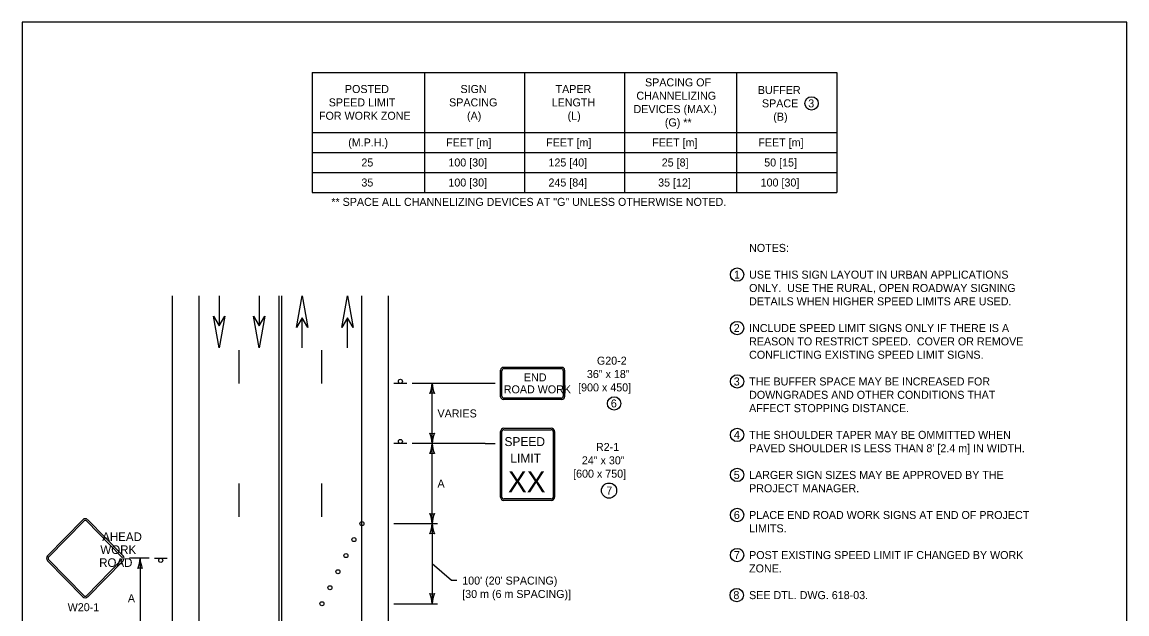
# Model space of a CAD drawing. Extents: x 49991.4 to 50021, y 49987.6 to 50011.4.
# Drawn here: x 50000.34 to 50008.61, y 50006.83 to 50011.26 of the extents above; entities that cross this region are included whole.
import ezdxf

# ---------------------------------------------------------------- set-up
doc = ezdxf.new("R2010")
doc.units = 0
for name, color, linetype in [('Level 1', 7, 'Continuous'), ('Level 2', 7, 'Continuous'), ('Level 3', 7, 'Continuous')]:
    doc.layers.add(name, color=color, linetype=linetype)

msp = doc.modelspace()

# ---------------------------------------------------------------- linework, layer by layer
at = {"layer": 'Level 1'}
for p, q in [((50001.4626, 50001.1514), (50001.4626, 50009.2134)), ((50001.6625, 50001.1514), (50001.6625, 50009.2134)), ((50001.8124, 50009.2134), (50001.8124, 50008.9875)), ((50001.8128, 50009.2134), (50001.8128, 50008.9875)), ((50002.1118, 50009.2134), (50002.1118, 50008.9875)), ((50002.1122, 50009.2134), (50002.1122, 50008.9875)), ((50002.2625, 50001.1514), (50002.2625, 50009.2134)), ((50002.2825, 50001.1514), (50002.2825, 50009.2134)), ((50002.8825, 50006.6477), (50002.8825, 50009.2134)), ((50003.0824, 50001.1514), (50003.0824, 50009.2134)), ((50002.4341, 50008.8233), (50002.4341, 50009.0492)), ((50002.4343, 50008.8233), (50002.4343, 50009.0492)), ((50002.7735, 50008.8232), (50002.7735, 50009.0491)), ((50002.7737, 50008.8232), (50002.7737, 50009.0491)), ((50001.9626, 50008.5574), (50001.9626, 50008.8074)), ((50002.5826, 50008.5574), (50002.5826, 50008.8074)), ((50003.9212, 50008.4574), (50003.9212, 50008.6574)), ((50003.9312, 50008.4624), (50003.9312, 50008.6524)), ((50004.3812, 50008.6774), (50003.9412, 50008.6774)), ((50004.3762, 50008.6674), (50003.9462, 50008.6674)), ((50004.3912, 50008.6524), (50004.3912, 50008.4624)), ((50004.4012, 50008.6574), (50004.4012, 50008.4574)), ((50003.2184, 50008.5574), (50003.1224, 50008.5574)), ((50004.3811, 50008.4374), (50003.9411, 50008.4374)), ((50004.3762, 50008.4474), (50003.9462, 50008.4474)), ((50003.9211, 50007.7066), (50003.9211, 50008.196)), ((50003.9316, 50007.7066), (50003.9316, 50008.196)), ((50003.9464, 50008.2213), (50004.3008, 50008.2213)), ((50003.9464, 50008.2108), (50004.3008, 50008.2108)), ((50004.1236, 50008.2213), (50004.1236, 50008.2213)), ((50004.3156, 50008.196), (50004.3156, 50007.7066)), ((50004.3261, 50008.196), (50004.3261, 50007.7066)), ((50003.2184, 50008.1074), (50003.1224, 50008.1074)), ((50001.9626, 50007.5574), (50001.9626, 50007.8074)), ((50002.5826, 50007.5574), (50002.5826, 50007.8074)), ((50004.3008, 50007.6918), (50003.9464, 50007.6918)), ((50004.3008, 50007.6812), (50003.9464, 50007.6812)), ((50000.5255, 50007.2658), (50000.7907, 50007.5365)), ((50000.5344, 50007.2571), (50000.7996, 50007.5278)), ((50000.8182, 50007.5278), (50001.0834, 50007.2571)), ((50000.827, 50007.5365), (50001.0922, 50007.2658)), ((50000.7996, 50006.9675), (50000.5344, 50007.2382)), ((50001.0834, 50007.2382), (50000.8182, 50006.9675)), ((50001.3266, 50007.2477), (50001.4226, 50007.2477)), ((50000.7907, 50006.9588), (50000.5255, 50007.2295)), ((50001.0922, 50007.2295), (50000.827, 50006.9588))]:
    msp.add_line(p, q, dxfattribs=at)
for points in [[(50008.6146, 50011.2628), (50000.3356, 50011.2628), (50000.3356, 50000.0624), (50008.6146, 50000.0624)], [(50002.3923, 50008.9769), (50002.4341, 50009.2134), (50002.4759, 50008.9769), (50002.4341, 50009.0491)], [(50002.7317, 50008.9768), (50002.7735, 50009.2133), (50002.8153, 50008.9768), (50002.7735, 50009.049)], [(50001.8544, 50009.0598), (50001.8128, 50008.8233), (50001.7708, 50009.0598), (50001.8128, 50008.9876)], [(50002.1538, 50009.0598), (50002.1122, 50008.8233), (50002.0702, 50009.0598), (50002.1122, 50008.9876)]]:
    msp.add_lwpolyline(points, close=True, dxfattribs=at)
for centre, radius in [((50003.1704, 50008.5726), 0.0152), ((50003.1704, 50008.1226), 0.0152), ((50002.8825, 50007.5074), 0.015), ((50002.8225, 50007.3874), 0.015), ((50001.3747, 50007.2325), 0.0152), ((50002.7626, 50007.2674), 0.015), ((50002.7026, 50007.1474), 0.015), ((50002.6426, 50007.0274), 0.015), ((50002.5826, 50006.9074), 0.015)]:
    msp.add_circle(centre, radius, dxfattribs=at)
for centre, radius, start, end in [((50003.9412, 50008.6574), 0.02, 90, 180), ((50003.9462, 50008.6524), 0.015, 90, 180), ((50004.3762, 50008.6524), 0.015, 360, 90), ((50004.3812, 50008.6574), 0.02, 360, 90), ((50003.9411, 50008.4574), 0.02, 180, 270), ((50003.9462, 50008.4624), 0.015, 180, 270), ((50004.3762, 50008.4624), 0.015, 270, 360), ((50004.3811, 50008.4574), 0.02, 270, 360), ((50003.9464, 50008.196), 0.0253, 90, 180), ((50003.9464, 50008.196), 0.0148, 90, 180), ((50004.3008, 50008.196), 0.0253, 0, 90), ((50004.3008, 50008.196), 0.0148, 0, 90), ((50003.9464, 50007.7066), 0.0253, 180, 270), ((50003.9464, 50007.7066), 0.0148, 180, 270), ((50004.3008, 50007.7066), 0.0148, 270, 360), ((50004.3008, 50007.7066), 0.0253, 270, 360)]:
    msp.add_arc(centre, radius, start, end, dxfattribs=at)
for centre, major_axis, ratio, start_param, end_param in [((50000.8089, 50007.5183), (0, 0.0258), 0.98963, 5.497795, 7.068583), ((50000.8089, 50007.5183), (0, 0.0134), 0.98, 5.497795, 7.068583), ((50000.5437, 50007.2477), (0, -0.0258), 0.98963, 3.926991, 5.497787), ((50000.5437, 50007.2477), (0, -0.0134), 0.98, 3.926991, 5.497787), ((50001.0741, 50007.2477), (0, -0.0134), 0.98, 0.785394, 2.356194), ((50001.0741, 50007.2477), (0, -0.0258), 0.98963, 0.785394, 2.356194), ((50000.8089, 50006.9771), (0, -0.0258), 0.98963, 5.497787, 7.068583), ((50000.8089, 50006.9771), (0, -0.0134), 0.98, 5.497787, 7.068583)]:
    msp.add_ellipse(centre, major_axis=major_axis, ratio=ratio, start_param=start_param, end_param=end_param, dxfattribs=at)
at = {"layer": 'Level 2'}
for p, q in [((50002.5101, 50010.8866), (50006.4401, 50010.8866)), ((50002.5101, 50010.8866), (50002.5101, 50009.9866)), ((50003.3501, 50010.8866), (50003.3501, 50009.9866)), ((50004.1001, 50010.8866), (50004.1001, 50009.9866)), ((50004.8501, 50010.8866), (50004.8501, 50009.9866)), ((50005.6901, 50010.8866), (50005.6901, 50009.9866)), ((50006.4401, 50010.8866), (50006.4401, 50009.9866)), ((50002.5101, 50010.4366), (50006.4401, 50010.4366)), ((50002.5101, 50010.2866), (50006.4401, 50010.2866)), ((50002.5101, 50010.1366), (50006.4401, 50010.1366)), ((50002.5101, 50009.9866), (50006.4401, 50009.9866))]:
    msp.add_line(p, q, dxfattribs=at)
for centre, radius in [((50006.2517, 50010.6543), 0.0501), ((50005.6934, 50009.3719), 0.0501), ((50005.6934, 50008.9719), 0.0501), ((50005.6934, 50008.5719), 0.0501), ((50004.7717, 50008.4073), 0.0501), ((50005.6934, 50008.1719), 0.0501), ((50005.6934, 50007.8719), 0.0501), ((50004.7341, 50007.7544), 0.0569), ((50005.6934, 50007.5719), 0.0501), ((50005.6934, 50007.2719), 0.0501), ((50005.6905, 50006.9719), 0.0501)]:
    msp.add_circle(centre, radius, dxfattribs=at)
at = {"layer": 'Level 3'}
for p, q in [((50003.8812, 50008.5574), (50003.2584, 50008.5574)), ((50003.4084, 50008.1074), (50003.4084, 50008.5574)), ((50003.8053, 50008.1074), (50003.2584, 50008.1074)), ((50003.4084, 50007.5074), (50003.4084, 50008.1074)), ((50003.1224, 50007.5074), (50003.4484, 50007.5074)), ((50003.4084, 50007.5074), (50003.4084, 50006.9074)), ((50001.2866, 50007.2477), (50001.1396, 50007.2477)), ((50001.2196, 50007.2477), (50001.2196, 50006.6477)), ((50003.1224, 50006.9074), (50003.4484, 50006.9074))]:
    msp.add_line(p, q, dxfattribs=at)
for points in [[(50003.8053, 50008.1074), (50003.8812, 50008.1074)], [(50003.5937, 50007.0806), (50003.5537, 50007.0806), (50003.4084, 50007.2074)]]:
    msp.add_lwpolyline(points, dxfattribs=at)
for centre, radius, start, end in [((50003.1863, 50008.5666), 0.2223, 337.45601, 357.63952), ((50003.6411, 50008.5689), 0.233, 182.82731, 202.07716), ((50003.4084, 50008.4292), 0.0548, 72.13882, 107.86118), ((50003.4084, 50008.2356), 0.0548, 252.13882, 287.86118), ((50003.1757, 50008.0959), 0.233, 2.82731, 22.07716), ((50003.6305, 50008.0982), 0.2223, 157.45601, 177.63952), ((50003.1863, 50008.1166), 0.2223, 337.45601, 357.63952), ((50003.6411, 50008.1189), 0.233, 182.82731, 202.07716), ((50003.4084, 50007.9792), 0.0548, 72.13882, 107.86118), ((50003.4084, 50007.6356), 0.0548, 252.13882, 287.86118), ((50003.1757, 50007.4959), 0.233, 2.82731, 22.07716), ((50003.6305, 50007.4982), 0.2223, 157.45601, 177.63952), ((50003.1863, 50007.5166), 0.2223, 337.45601, 357.63952), ((50003.1863, 50007.5166), 0.2223, 337.45601, 357.63952), ((50003.6411, 50007.5189), 0.233, 182.82731, 202.07716), ((50003.6411, 50007.5189), 0.233, 182.82731, 202.07716), ((50003.4084, 50007.3792), 0.0548, 72.13882, 107.86118), ((50003.4084, 50007.3792), 0.0548, 72.13882, 107.86118), ((50000.9975, 50007.2569), 0.2223, 337.45601, 357.63952), ((50001.4523, 50007.2592), 0.233, 182.82731, 202.07716), ((50001.2196, 50007.1195), 0.0548, 72.13882, 107.86118), ((50003.4084, 50007.0356), 0.0548, 252.13882, 287.86118), ((50003.1757, 50006.8959), 0.233, 2.82731, 22.07716), ((50003.4084, 50007.0356), 0.0548, 252.13882, 287.86118), ((50003.1757, 50006.8959), 0.233, 2.82731, 22.07716), ((50003.6305, 50006.8982), 0.2223, 157.45601, 177.63952), ((50003.6305, 50006.8982), 0.2223, 157.45601, 177.63952)]:
    msp.add_arc(centre, radius, start, end, dxfattribs=at)

# ---------------------------------------------------------------- texts
at = {"layer": 'Level 1'}
for s, height, p in [('END', 0.06, (50004.096, 50008.5728)), ('ROAD WORK', 0.06, (50003.9453, 50008.4828)), ('AHEAD', 0.06453, (50000.9359, 50007.3767)), ('WORK', 0.06453, (50000.9221, 50007.2799)), ('ROAD', 0.06453, (50000.9131, 50007.1832))]:
    msp.add_text(s, height=height, rotation=360, dxfattribs=at).set_placement(p)
for s, height, p in [('SPEED', 0.06695, (50003.9505, 50008.0881)), ('LIMIT', 0.06695, (50003.9948, 50007.9643)), ('XX', 0.15772, (50003.9765, 50007.7423))]:
    msp.add_text(s, height=height, dxfattribs=at).set_placement(p)
at = {"layer": 'Level 2'}
for s, p in [('POSTED', (50002.7548, 50010.7316)), ('SIGN', (50003.6208, 50010.7316)), ('TAPER', (50004.3334, 50010.7316)), ('SPACING OF', (50005.0036, 50010.7816)), ('CHANNELIZING', (50004.9389, 50010.6816)), ('BUFFER', (50005.849, 50010.7243)), ('SPEED LIMIT', (50002.6335, 50010.6316)), ('SPACING', (50003.5357, 50010.6316)), ('LENGTH', (50004.3042, 50010.6316)), ('DEVICES (MAX.)', (50004.9175, 50010.5816)), ('SPACE', (50005.8798, 50010.6243)), ('3', (50006.2267, 50010.6244)), ('FOR WORK ZONE', (50002.5605, 50010.5316)), ('(A)', (50003.6698, 50010.5316)), ('(L)', (50004.4235, 50010.5316)), ('(G) **', (50005.1522, 50010.4816)), ('(B)', (50005.965, 50010.5243)), ('(M.P.H.)', (50002.7794, 50010.3316)), ('FEET [m]', (50003.5128, 50010.3316)), ('FEET [m]', (50004.2628, 50010.3316)), ('FEET [m]', (50005.0578, 50010.3316)), ('FEET [m]', (50005.8528, 50010.3316)), ('25', (50002.8783, 50010.1816)), ('100 [30]', (50003.53, 50010.1816)), ('125 [40]', (50004.28, 50010.1816)), ('25 [8]', (50005.1288, 50010.1816)), ('50 [15]', (50005.8969, 50010.1816)), ('35', (50002.8783, 50010.0316)), ('100 [30]', (50003.53, 50010.0316)), ('245 [84]', (50004.28, 50010.0316)), ('35 [12]', (50005.1019, 50010.0316)), ('100 [30]', (50005.87, 50010.0316)), ('** SPACE ALL CHANNELIZING DEVICES AT "G" UNLESS OTHERWISE NOTED.', (50002.6529, 50009.8866)), ('NOTES:', (50005.7835, 50009.5419)), ('1', (50005.6707, 50009.3419)), ('USE THIS SIGN LAYOUT IN URBAN APPLICATIONS', (50005.7835, 50009.3419)), ('ONLY.  USE THE RURAL, OPEN ROADWAY SIGNING', (50005.7835, 50009.2419)), ('DETAILS WHEN HIGHER SPEED LIMITS ARE USED.', (50005.7835, 50009.1419)), ('2', (50005.6684, 50008.942)), ('INCLUDE SPEED LIMIT SIGNS ONLY IF THERE IS A', (50005.7835, 50008.9419)), ('REASON TO RESTRICT SPEED.  COVER OR REMOVE', (50005.7835, 50008.8419)), ('CONFLICTING EXISTING SPEED LIMIT SIGNS.', (50005.7835, 50008.7419)), ('G20-2', (50004.6431, 50008.6974)), ('36" x 18"', (50004.5679, 50008.5974)), ('[900 x 450]', (50004.5023, 50008.4974)), ('3', (50005.6684, 50008.542)), ('THE BUFFER SPACE MAY BE INCREASED FOR', (50005.7835, 50008.5419)), ('DOWNGRADES AND OTHER CONDITIONS THAT', (50005.7835, 50008.4419)), ('6', (50004.7474, 50008.3774)), ('AFFECT STOPPING DISTANCE.', (50005.7835, 50008.3419)), ('4', (50005.6696, 50008.142)), ('THE SHOULDER TAPER MAY BE OMMITTED WHEN', (50005.7835, 50008.1419)), ('R2-1', (50004.6359, 50008.0513)), ("PAVED SHOULDER IS LESS THAN 8' [2.4 m] IN WIDTH.", (50005.7835, 50008.0419)), ('24" x 30"', (50004.5304, 50007.9513)), ('[600 x 750]', (50004.4648, 50007.8513)), ('5', (50005.6686, 50007.842)), ('LARGER SIGN SIZES MAY BE APPROVED BY THE', (50005.7835, 50007.8419)), ('7', (50004.7133, 50007.7244)), ('PROJECT MANAGER.', (50005.7835, 50007.7419)), ('6', (50005.669, 50007.542)), ('PLACE END ROAD WORK SIGNS AT END OF PROJECT', (50005.7835, 50007.5419)), ('LIMITS.', (50005.7835, 50007.4419)), ('7', (50005.6698, 50007.242)), ('POST EXISTING SPEED LIMIT IF CHANGED BY WORK', (50005.7835, 50007.2419)), ('ZONE.', (50005.7835, 50007.1419)), ("100' (20' SPACING)", (50003.6337, 50007.0506)), ('[30 m (6 m SPACING)]', (50003.6337, 50006.9506)), ('8', (50005.6657, 50006.942)), ('SEE DTL. DWG. 618-03.', (50005.7835, 50006.9419)), ('W20-1', (50000.6773, 50006.8513))]:
    msp.add_text(s, height=0.06, dxfattribs=at).set_placement(p)
for s, p in [('VARIES', (50003.4484, 50008.3024)), ('A', (50003.4484, 50007.7774)), ('A', (50001.1281, 50006.9177))]:
    msp.add_text(s, height=0.06, rotation=360, dxfattribs=at).set_placement(p)

doc.saveas('drawing.dxf')
